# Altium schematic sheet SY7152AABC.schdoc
size 127 x 101 mm
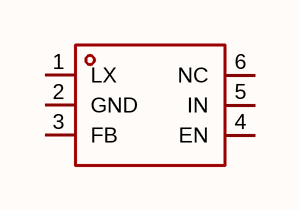
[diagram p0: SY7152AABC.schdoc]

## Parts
U?  sy7152aabc  [SOT-23-6_L2.9-W1.6-P0.95-LS2.8-BL]  (value not drawn)

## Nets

Not connected (* = marked no-connect by the designer): U? 1(LX) 2(GND) 3(FB) 4(EN) 5(IN) 6(NC)

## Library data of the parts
U? = sy7152aabc: 功能类型:升压型;工作电压:3V~8V;输出电压:600mV~16V;输出电流:2A;输出类型:可调;; Manufacturer: Silergy(矽力杰); AddInBom: yes; ModelId: 18da8f6c14a34920b3e136b5c401a119; ModelName: SOT-23-6_L2.9-W1.6-H1.5-LS2.8-P0.95; ModelTransform: 110.236,113.364,0,90,0,0,0.0005,0.0005,0; Function: 升压型; Voltage - Supply: 3V~8V; Output Current: 2A; Frequency - Switching: 1MHz; Synchronous Rectifier: 否; Number of Outputs: 1; Topology: 升压式; Quiescent Current: 100uA; Switch tube (built-in/external): 内置; Output Type: 可调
